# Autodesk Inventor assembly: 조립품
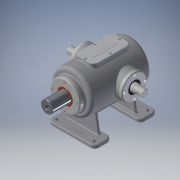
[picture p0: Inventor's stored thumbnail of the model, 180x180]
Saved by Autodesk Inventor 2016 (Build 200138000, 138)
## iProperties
Created: 2018-11
Part Number: 조립품
Material: 일반
Document SubType Name: Assembly
Designer: user
Author: user
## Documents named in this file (15)
- C:\Users\user\Desktop\381121V1002\조립품.iam
- C:\Users\user\Desktop\381121V1002\본체.ipt
- C:\Users\user\Desktop\381121V1002\베어링 6205.ipt
- 베어링 6205.ipt
- C:\Users\user\Desktop\381121V1002\볼트 M4x0.7.ipt
- C:\Users\user\Desktop\381121V1002\부시.ipt
- C:\Users\user\Desktop\381121V1002\상부커버.ipt
- C:\Users\user\Desktop\381121V1002\슬라이드 커버.ipt
- C:\Users\user\Desktop\381121V1002\슬라이드.ipt
- C:\Users\user\Desktop\381121V1002\오일실.ipt
- 오일실.ipt
- C:\Users\user\Desktop\381121V1002\육각머리볼트 M4.ipt
- C:\Users\user\Desktop\381121V1002\축 커버.ipt
- C:\Users\user\Desktop\381121V1002\편심축.ipt
- C:\Users\user\Desktop\381121V1002\가변스프링.ipt
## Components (13 placed, 2 different names)
1. 가변스프링:1
2. M4x0.7:1
3. M4x0.7:4
4. M4x0.7:5
5. M4x0.7:6
6. M4x0.7:2
7. M4x0.7:7
8. M4x0.7:8
9. M4x0.7:9
10. M4x0.7:3
11. M4x0.7:10
12. M4x0.7:11
13. M4x0.7:12
